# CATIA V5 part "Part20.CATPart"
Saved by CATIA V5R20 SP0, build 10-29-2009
Part number: 9TS1606M6
Revision: ANY
Definition: UNKNOWN
Nomenclature: 9TS1606M6
Source: Unknown
Bounding box of the stored display mesh (mm): x -8 to 8, y -8 to 8, z 0 to 6
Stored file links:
  C:\Users\Utente\Desktop\IO LAVORO\3D X SITO CF\CUMSA\3D files GR\GR 283432-15\Part20.CATPart
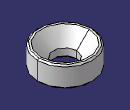
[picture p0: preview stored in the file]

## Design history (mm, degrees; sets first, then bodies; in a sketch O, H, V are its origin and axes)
Body1 "Chaflán1" (main body)
  Solid1: solid without history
